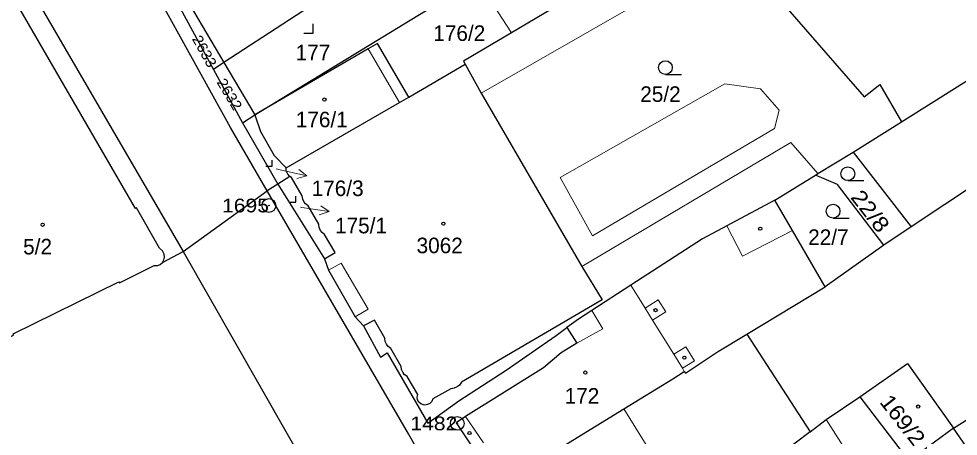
# Model space of a CAD drawing. Extents: x -679733 to -673243, y -1075091 to -1066557.
# Drawn here: x -676427.8 to -676325, y -1071507.3 to -1071461.6 of the extents above; entities that cross this region are included whole.
import ezdxf
from ezdxf.enums import TextEntityAlignment as Align

# ---------------------------------------------------------------- set-up
doc = ezdxf.new("R2010")
doc.units = 0
doc.header["$LTSCALE"] = 0.68
for name, color, linetype, lineweight in [('1', 7, 'Continuous', 25), ('3', 7, 'Continuous', 25), ('4', 7, 'Continuous', 13), ('5', 7, 'Continuous', 25), ('7', 7, 'Continuous', 13), ('8', 7, 'Continuous', 25)]:
    doc.layers.add(name, color=color, linetype=linetype, lineweight=lineweight)
doc.layers.add('2', color=7, linetype='Continuous')

msp = doc.modelspace()

# ---------------------------------------------------------------- linework, layer by layer
at = {"layer": '1'}
for p, q in [((-676385.14, -1071470.18), (-676378.99, -1071466.58)), ((-676403.36, -1071472.99), (-676399.47, -1071479.69)), ((-676336.54, -1071476.22), (-676330.2, -1071484.39)), ((-676345.1, -1071481.46), (-676340.65, -1071478.73)), ((-676409.82, -1071487.07), (-676400.64, -1071480.43)), ((-676399.47, -1071479.69), (-676400.64, -1071480.43)), ((-676412.1, -1071488.28), (-676409.82, -1071487.07)), ((-676348.17, -1071496.11), (-676341.26, -1071506.79)), ((-676335.82, -1071502.99), (-676330.43, -1071509.97))]:
    msp.add_line(p, q, dxfattribs=at)
for points in [[(-676400.64, -1071480.43), (-676404.65, -1071473.51), (-676415.78, -1071453.37), (-676425.35, -1071436.91), (-676444.25, -1071404.92), (-676453.53, -1071391.57), (-676458.63, -1071385.05), (-676473.24, -1071365.27), (-676485.03, -1071348.15), (-676497.15, -1071331.02), (-676507.56, -1071316.17), (-676512.86, -1071309.51), (-676528.01, -1071291.25), (-676530.94, -1071288.81)], [(-676462.44, -1071396.87), (-676454.68, -1071408.62), (-676448.67, -1071419.37), (-676435.44, -1071442.2), (-676426.52, -1071458.32), (-676409.82, -1071487.07)], [(-676381.07, -1071440.55), (-676382.86, -1071441.83), (-676383.58, -1071442.35), (-676402.84, -1071454.75), (-676409.66, -1071459.12), (-676405.37, -1071466.39)], [(-676370.94, -1071444.46), (-676371.9, -1071445.04), (-676373.05, -1071445.76), (-676375.24, -1071447.16), (-676383.85, -1071452.35), (-676405.37, -1071466.39), (-676402.01, -1071472.1)], [(-676331.25, -1071472.89), (-676304.11, -1071455.79), (-676308.62, -1071448.76)], [(-676402.01, -1071472.1), (-676383.34, -1071460.74), (-676376.5, -1071456.41), (-676367.76, -1071450.99), (-676366.58, -1071450.38)], [(-676352.55, -1071450.35), (-676350.15, -1071453.1), (-676335.33, -1071470.14), (-676333.64, -1071468.78), (-676331.25, -1071472.89)], [(-676412.43, -1071486.72), (-676414.93, -1071482.28), (-676415.03, -1071482.35), (-676428.2, -1071459.64), (-676428.02, -1071459.53), (-676429.93, -1071456.15)], [(-676362.41, -1071456.29), (-676373.91, -1071463.13), (-676379.15, -1071466.25), (-676378.99, -1071466.58)], [(-676410.39, -1071459.6), (-676410.23, -1071459.88), (-676410.4, -1071459.97), (-676406.53, -1071467.14)], [(-676385.14, -1071470.18), (-676388.57, -1071464.31), (-676389.61, -1071464.91), (-676402.01, -1071472.1)], [(-676335.82, -1071502.99), (-676330.59, -1071499.32), (-676325.57, -1071506.42), (-676287.3, -1071482.24), (-676289.11, -1071479.48), (-676299.04, -1071464.32)], [(-676299.04, -1071464.32), (-676309.3, -1071470.91), (-676309.64, -1071470.38), (-676311.97, -1071471.88), (-676311.79, -1071472.15), (-676330.2, -1071484.39)], [(-676405.37, -1071466.39), (-676406.53, -1071467.14), (-676403.36, -1071472.99), (-676402.01, -1071472.1)], [(-676378.99, -1071466.58), (-676377.24, -1071469.73), (-676366.23, -1071488.72), (-676363.99, -1071492.38), (-676379.37, -1071501.39)], [(-676398.57, -1071477.91), (-676386.18, -1071470.78), (-676385.14, -1071470.18)], [(-676402.01, -1071472.1), (-676401.39, -1071473.93), (-676399.87, -1071476.56), (-676398.57, -1071477.91)], [(-676340.65, -1071478.73), (-676340.42, -1071478.53), (-676336.54, -1071476.22), (-676331.25, -1071472.89)], [(-676398.16, -1071478.86), (-676398.385, -1071478.618), (-676398.429, -1071478.547), (-676398.548, -1071478.239), (-676398.57, -1071477.91)], [(-676396.8, -1071480.99), (-676397.97, -1071478.98), (-676398.16, -1071478.86), (-676399.47, -1071479.69), (-676394.39, -1071487.87)], [(-676333.18, -1071486.39), (-676338.24, -1071479.75), (-676340.65, -1071478.73)], [(-676358.61, -1071600.83), (-676364.98, -1071562.95), (-676369.16, -1071542.83), (-676371.77, -1071533.39), (-676374.14, -1071526.78), (-676385.2, -1071507.04), (-676400.64, -1071480.43)], [(-676396.17, -1071482.08), (-676396.449, -1071481.868), (-676396.614, -1071481.658), (-676396.755, -1071481.337), (-676396.8, -1071480.99)], [(-676345.1, -1071481.46), (-676350.35, -1071484.25), (-676353.04, -1071485.68), (-676360.86, -1071490.76), (-676365.14, -1071493.54), (-676366.57, -1071494.46), (-676367.85, -1071495.38)], [(-676339.61, -1071490.93), (-676343.17, -1071484.79), (-676345.1, -1071481.46)], [(-676394.36, -1071485.21), (-676394.644, -1071484.993), (-676394.819, -1071484.771), (-676394.963, -1071484.444), (-676395.01, -1071484.09), (-676396.17, -1071482.08)], [(-676330.2, -1071484.39), (-676333.18, -1071486.39), (-676339.61, -1071490.93)], [(-676394.39, -1071487.87), (-676393.22, -1071487.18), (-676394.36, -1071485.21)], [(-676412.1, -1071488.28), (-676411.946, -1071487.992), (-676411.887, -1071487.681), (-676411.925, -1071487.357), (-676412.06, -1071487.06), (-676412.11, -1071486.99), (-676412.43, -1071486.72)], [(-676409.82, -1071487.07), (-676395.79, -1071511.68), (-676384.03, -1071532.68), (-676381.89, -1071539.87), (-676376.19, -1071569.34), (-676368.13, -1071616.48), (-676365.86, -1071630.87), (-676366.52, -1071654.54), (-676369.19, -1071723.74), (-676369.58, -1071729.58), (-676368.92, -1071732.38)], [(-676431.4, -1071497.6), (-676431.1, -1071497.47), (-676431.05, -1071497.56), (-676428.38, -1071496.23), (-676428.44, -1071496.09), (-676416.87, -1071490.38), (-676416.81, -1071490.51), (-676413.01, -1071488.59)], [(-676413.01, -1071488.59), (-676412.705, -1071488.605), (-676412.617, -1071488.59), (-676412.333, -1071488.478), (-676412.1, -1071488.28)], [(-676394.39, -1071487.87), (-676393.94, -1071489.1), (-676391.01, -1071494.23), (-676390.11, -1071495.22)], [(-676374.22, -1071512.02), (-676361.61, -1071504.29), (-676356.25, -1071501.01), (-676355.01, -1071500.2), (-676354.9, -1071500.37), (-676351.39, -1071498.07), (-676348.17, -1071496.11), (-676339.61, -1071490.93)], [(-676387.77, -1071496.56), (-676388.92, -1071494.6), (-676390.11, -1071495.22)], [(-676390.11, -1071495.22), (-676388.26, -1071498.62), (-676387.51, -1071498.16), (-676383.06, -1071505.87), (-676379.69, -1071503.4), (-676374.51, -1071500.06), (-676369.04, -1071496.25), (-676367.85, -1071495.38)], [(-676367.85, -1071495.38), (-676366.78, -1071497.11), (-676368.48, -1071498.17), (-676370.4, -1071499.82), (-676378.95, -1071505.12), (-676379.98, -1071505.81), (-676378.22, -1071508.45), (-676377.12, -1071510.08), (-676375.33, -1071512.76), (-676374.22, -1071512.02)], [(-676387.12, -1071497.68), (-676387.402, -1071497.477), (-676387.6, -1071497.227), (-676387.733, -1071496.906), (-676387.77, -1071496.56)], [(-676385.32, -1071500.76), (-676385.601, -1071500.57), (-676385.612, -1071500.56), (-676385.821, -1071500.294), (-676385.944, -1071499.978), (-676385.97, -1071499.64), (-676387.12, -1071497.68)], [(-676382.53, -1071503.2), (-676382.642, -1071503.471), (-676382.838, -1071503.689), (-676383.096, -1071503.829), (-676383.386, -1071503.873), (-676383.545, -1071503.856), (-676383.818, -1071503.748), (-676384.039, -1071503.555), (-676384.182, -1071503.298), (-676384.231, -1071503.009), (-676384.18, -1071502.72), (-676385.32, -1071500.76)], [(-676379.37, -1071501.39), (-676379.592, -1071501.685), (-676379.847, -1071501.888), (-676380.185, -1071502.037), (-676380.55, -1071502.09), (-676382.53, -1071503.2)], [(-676341.26, -1071506.79), (-676339.51, -1071505.46), (-676335.82, -1071502.99)], [(-676341.26, -1071506.79), (-676344.51, -1071509.28), (-676346.31, -1071510.51), (-676348.89, -1071512.29), (-676354.42, -1071515.86), (-676366.93, -1071523.92)], [(-676316.72, -1071519.24), (-676325.57, -1071506.42), (-676330.43, -1071509.97)]]:
    msp.add_lwpolyline(points, dxfattribs=at)
at = {"layer": '3'}
for p, q in [((-676357.073, -1071467.7), (-676355.323, -1071467.7)), ((-676337.123, -1071479.32), (-676335.373, -1071479.32)), ((-676338.743, -1071483.41), (-676336.993, -1071483.41))]:
    msp.add_line(p, q, dxfattribs=at)
for points in [[(-676396.621, -1071463.17), (-676395.62, -1071463.17), (-676395.62, -1071462.17)], [(-676400.781, -1071477.73), (-676400.11, -1071477.73), (-676400.11, -1071477.06)], [(-676398.191, -1071481.67), (-676397.52, -1071481.67), (-676397.52, -1071481)]]:
    msp.add_lwpolyline(points, dxfattribs=at)
for centre in [(-676357.0729, -1071466.9498), (-676337.1229, -1071478.5698), (-676338.7429, -1071482.6598)]:
    msp.add_circle(centre, 0.75, dxfattribs=at)
at = {"layer": '4'}
for p, q in [((-676377.24, -1071469.73), (-676353.92, -1071456.38)), ((-676376.36, -1071459.34), (-676373.91, -1071463.13)), ((-676389.61, -1071464.91), (-676386.18, -1071470.78)), ((-676368.6, -1071478.99), (-676350.58, -1071468.73)), ((-676350.58, -1071468.73), (-676346.69, -1071469.26)), ((-676346.69, -1071469.26), (-676344.65, -1071471.61)), ((-676344.65, -1071471.61), (-676345.14, -1071473.63)), ((-676345.14, -1071473.63), (-676365.06, -1071485.34)), ((-676366.23, -1071488.72), (-676343.37, -1071475.16)), ((-676343.37, -1071475.16), (-676340.42, -1071478.53)), ((-676365.06, -1071485.34), (-676368.6, -1071478.99)), ((-676350.35, -1071484.25), (-676348.63, -1071487.6)), ((-676348.63, -1071487.6), (-676343.17, -1071484.79)), ((-676393.94, -1071489.1), (-676392.54, -1071488.35)), ((-676392.54, -1071488.35), (-676389.6, -1071493.4)), ((-676360.86, -1071490.76), (-676359.3, -1071493.26)), ((-676359.3, -1071493.26), (-676357.86, -1071492.37)), ((-676357.86, -1071492.37), (-676357.04, -1071493.69)), ((-676389.6, -1071493.4), (-676391.01, -1071494.23)), ((-676365.14, -1071493.54), (-676363.91, -1071495.54)), ((-676359.3, -1071493.26), (-676358.49, -1071494.58)), ((-676357.04, -1071493.69), (-676358.49, -1071494.58)), ((-676358.49, -1071494.58), (-676356.17, -1071498.32)), ((-676366.78, -1071497.11), (-676363.91, -1071495.54)), ((-676356.17, -1071498.32), (-676354.85, -1071497.51)), ((-676354.85, -1071497.51), (-676353.9, -1071499.04)), ((-676356.17, -1071498.32), (-676355.22, -1071499.85)), ((-676355.22, -1071499.85), (-676353.9, -1071499.04)), ((-676355.22, -1071499.85), (-676355.01, -1071500.2)), ((-676378.95, -1071505.12), (-676376.97, -1071508.01)), ((-676361.61, -1071504.29), (-676354.42, -1071515.86)), ((-676339.51, -1071505.46), (-676334.74, -1071512.89))]:
    msp.add_line(p, q, dxfattribs=at)
at = {"layer": '5'}
for centre in [(-676394.3768, -1071470.4492), (-676425.2068, -1071484.1492), (-676381.3668, -1071484.0192), (-676346.7068, -1071484.5792), (-676358.1568, -1071493.4892), (-676355.0068, -1071498.6892), (-676365.8368, -1071500.3192), (-676329.4268, -1071504.0392), (-676378.5068, -1071506.9392)]:
    msp.add_circle(centre, 0.175, dxfattribs=at)
at = {"layer": '7'}
for p, q in [((-676396.306, -1071478.805), (-676397.169, -1071478.092)), ((-676393.876, -1071482.709), (-676394.787, -1071482.058))]:
    msp.add_line(p, q, dxfattribs=at)
for points in [[(-676399.65, -1071478.03), (-676399.23, -1071478.13), (-676396.306, -1071478.805), (-676397.394, -1071479.068)], [(-676396.98, -1071482.22), (-676396.84, -1071482.24), (-676393.876, -1071482.709), (-676394.943, -1071483.047)]]:
    msp.add_lwpolyline(points, dxfattribs=at)
at = {"layer": '8'}
for centre, radius in [((-676400.45, -1071482.0398), 0.75), ((-676400.45, -1071482.0398), 0.03), ((-676379.85, -1071505.8898), 0.75), ((-676379.85, -1071505.8898), 0.03)]:
    msp.add_circle(centre, radius, dxfattribs=at)

# ---------------------------------------------------------------- texts
at = {"layer": '2'}
for s, p in [('176/2', (-676379.63, -1071464.029)), ('177', (-676395.639, -1071466.15)), ('25/2', (-676357.62, -1071470.7)), ('176/1', (-676394.67, -1071473.479)), ('22/7', (-676339.25, -1071486.35)), ('3062', (-676381.77, -1071487.259)), ('172', (-676366.209, -1071503.72))]:
    msp.add_text(s, height=1.7, dxfattribs=at).set_placement(p, align=Align.CENTER)
for s, height, rotation, width, p in [('2633', 1.139, 299, 1.1, (-676407.9958, -1071465.4289)), ('2632', 1.139, 301, 1.1, (-676405.2505, -1071470.1482)), ('22/8', 1.7, 308, 1.15, (-676335.3368, -1071483.1717)), ('169/2', 1.7, 308, 1.1, (-676331.7967, -1071506.0317))]:
    msp.add_text(s, height=height, rotation=rotation, dxfattribs=dict(at, width=width)).set_placement(p, align=Align.CENTER)
for s, p in [('176/3', (-676395.78, -1071481.003)), ('175/1', (-676393.22, -1071485.083)), ('5/2', (-676427.34, -1071487.39))]:
    msp.add_text(s, height=1.7, dxfattribs=at).set_placement(p)
at = {"layer": '8', "width": 1.15}
for s, p in [('1695', (-676400.449, -1071482.79)), ('1482', (-676379.849, -1071506.639))]:
    msp.add_text(s, height=1.5, dxfattribs=at).set_placement(p, align=Align.RIGHT)

doc.saveas('drawing.dxf')
